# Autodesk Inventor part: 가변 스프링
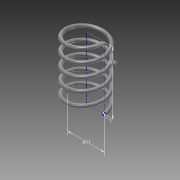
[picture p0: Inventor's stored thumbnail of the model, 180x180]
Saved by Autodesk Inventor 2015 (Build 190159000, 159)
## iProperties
Created: 2015-10
Part Number: 가변 스프링
Material: 강철, 연강
Document SubType Name: Modeling
Designer: PHO-02
Density: 7.85 g/cm^3
Appearance: 반연마
Mass: 1.05364 g
Surface Area: 5.43134 cm^2
Volume: 0.134222 cm^3
Author: PHO-02
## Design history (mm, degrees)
sketch "스케치2"
  geometry: L1 (0, 0)-(-5.5, 0); L2 (-5.5, 0)-(-5.5, 18.948); L3 (-5.5, 18.948)-(0, 18.948); L4 (0, 18.948)-(0, 0); C1 r 0.5 at (-5.5, 0)
  constraints: 8 end point, 2 parallel, 1 centre point, 1 coincident, 1 horizontal, 1 perpendicular
  dimensions: "d0" = 18.94782 distance between parallel lines of L3 L1 (derived); "d1" = 11 diameter of L2 L4; "d2" = 1 diameter of C1
feature "코일1" sketch "스케치2" pitch "d3" = 10; turns "d5" = 5; dims "d4" = 18.94782 (= d0), "d6" = 0, angle "d7" = 90 deg, angle "d8" = 90 deg, "d9" = 0, "d10" = 0
sketch "스케치3"
  geometry: L1 (6, 0)-(5, 0) reference; 1 further point
  constraints: 1 horizontal alignment
extrude "돌출1" cut sketch "스케치3" stored distance "d11" = 10; taper "d12" = 0 deg
node "작업 평면1"
sketch "스케치4"
  geometry: L1 (-0.5, 0)-(0.5, 0) reference; 1 further point
  constraints: 1 horizontal alignment
extrude "돌출2" cut sketch "스케치4" stored distance "d14" = 10; taper "d15" = 0 deg
node "솔리드1"
node "절단 모서리 투영1"
node "절단 모서리 투영2"
other parameters: "d13" = 90 deg
